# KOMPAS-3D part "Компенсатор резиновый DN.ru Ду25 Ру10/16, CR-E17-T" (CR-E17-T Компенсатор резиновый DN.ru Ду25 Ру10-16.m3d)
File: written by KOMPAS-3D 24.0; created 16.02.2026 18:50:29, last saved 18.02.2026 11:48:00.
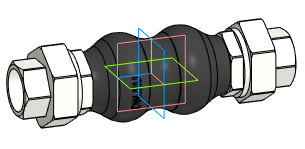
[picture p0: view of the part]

Document properties: Автор: DN.RU; Полное имя файла: CR-E17-T Компенсатор резиновый DN.ru Ду25 Ру10-16.cdw

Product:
- Body: Твердое тело1  | qty 1
    Масса: 2.292804
- Part/product: Компенсатор резиновый DN.ru Ду25 Ру10/16  | designation CR-E17-T
    Масса: 1.25
    Раздел спецификации: Прочие изделия
    Форматы листов документа: A3
    Комментарий: D140-02211
    Примечание: D140-02211
    additional columns: Типовые

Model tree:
1. Твердое тело1  (labels: Твердое тело1)

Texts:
  CR-E17-T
